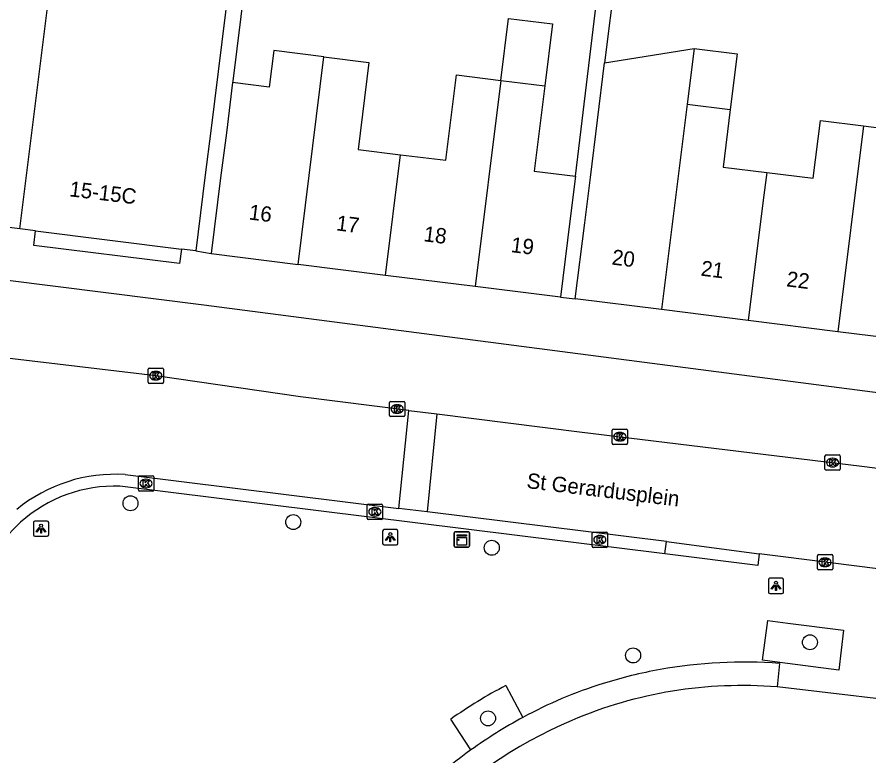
# Model space of a CAD drawing. Extents: x 161696 to 162377, y 380761 to 381673.
# Drawn here: x 162038 to 162093.7, y 381316.7 to 381365 of the extents above; entities that cross this region are included whole.
import ezdxf

# ---------------------------------------------------------------- set-up
doc = ezdxf.new("R2010")
doc.units = 0
for name, color, linetype in [('IMGEO_Boom', 7, 'Continuous'), ('IMGEO_Kast', 7, 'Continuous'), ('IMGEO_Kolk', 7, 'Continuous'), ('IMGEO_Lichtpunt', 7, 'Continuous'), ('IMGEO_Openbare_ruimte_label', 7, 'Continuous'), ('IMGEO_Pand', 7, 'Continuous'), ('IMGEO_Pand_nummerreeks', 7, 'Continuous'), ('IMGEO_Parkeervlak_open', 7, 'Continuous'), ('IMGEO_Rijbaan_lokaal_open', 7, 'Continuous'), ('IMGEO_Voetpad_open', 7, 'Continuous')]:
    doc.layers.add(name, color=color, linetype=linetype)

msp = doc.modelspace()

# ---------------------------------------------------------------- linework, layer by layer
at = {"layer": 'IMGEO_Boom'}
for centre in [(162045.423, 381333.251), (162056.062, 381332.022), (162069.042, 381330.344), (162089.839, 381324.168), (162078.282, 381323.308), (162068.796, 381319.197)]:
    msp.add_circle(centre, 0.489, dxfattribs=at)
at = {"layer": 'IMGEO_Kast'}
for p, q in [((162066.584, 381330.468), (162066.584, 381331.309)), ((162066.584, 381331.309), (162066.584, 381330.468)), ((162066.659, 381331.393), (162067.5, 381331.393)), ((162067.5, 381331.393), (162066.659, 381331.393)), ((162067.584, 381331.318), (162067.584, 381330.477)), ((162067.584, 381330.477), (162067.584, 381331.318)), ((162067.509, 381330.393), (162066.668, 381330.393)), ((162066.668, 381330.393), (162067.509, 381330.393))]:
    msp.add_line(p, q, dxfattribs=at)
for points in [[(162066.779, 381331.183), (162067.379, 381331.183), (162067.379, 381331.098), (162066.779, 381331.098), (162066.779, 381331.183)], [(162066.779, 381331.008), (162067.379, 381331.008), (162067.379, 381330.519), (162066.779, 381330.519), (162066.779, 381331.008)]]:
    msp.add_lwpolyline(points, dxfattribs=at)
msp.add_circle((162066.863, 381330.857), 0.0377, dxfattribs=at)
for centre, start, end in [((162066.662, 381331.315), 92.4484, 184.2845), ((162066.662, 381331.315), 92.4484, 184.2845), ((162067.506, 381331.315), 2.4484, 94.2845), ((162067.506, 381331.315), 2.4484, 94.2845), ((162066.662, 381330.471), 182.4484, 274.2845), ((162066.662, 381330.471), 182.4484, 274.2845), ((162067.506, 381330.471), 272.4484, 4.2845), ((162067.506, 381330.471), 272.4484, 4.2845)]:
    msp.add_arc(centre, 0.0779, start, end, dxfattribs=at)
at = {"layer": 'IMGEO_Kolk'}
for p, q in [((162046.575, 381341.162), (162046.575, 381342.014)), ((162046.65, 381342.088), (162047.502, 381342.088)), ((162047.063, 381341.868), (162047.088, 381341.868)), ((162047.576, 381342.014), (162047.576, 381341.162)), ((162047.086, 381341.308), (162047.061, 381341.308)), ((162047.502, 381341.088), (162046.65, 381341.088)), ((162062.355, 381338.986), (162062.355, 381339.838)), ((162062.43, 381339.912), (162063.282, 381339.912)), ((162062.843, 381339.692), (162062.868, 381339.692)), ((162063.356, 381339.838), (162063.356, 381338.986)), ((162062.866, 381339.132), (162062.841, 381339.132)), ((162063.282, 381338.912), (162062.43, 381338.912)), ((162076.916, 381337.175), (162076.916, 381338.027)), ((162076.991, 381338.101), (162077.843, 381338.101)), ((162077.404, 381337.881), (162077.429, 381337.881)), ((162077.917, 381338.027), (162077.917, 381337.175)), ((162077.427, 381337.321), (162077.402, 381337.321)), ((162077.843, 381337.101), (162076.991, 381337.101)), ((162090.824, 381335.484), (162090.824, 381336.336)), ((162090.899, 381336.41), (162091.751, 381336.41)), ((162091.825, 381336.336), (162091.825, 381335.484)), ((162091.312, 381336.19), (162091.337, 381336.19)), ((162091.751, 381335.41), (162090.899, 381335.41)), ((162091.335, 381335.63), (162091.31, 381335.63)), ((162045.939, 381334.119), (162045.939, 381334.971)), ((162046.014, 381335.045), (162046.866, 381335.045)), ((162046.427, 381334.825), (162046.452, 381334.825)), ((162046.94, 381334.971), (162046.94, 381334.119)), ((162046.866, 381334.045), (162046.014, 381334.045)), ((162046.45, 381334.265), (162046.425, 381334.265)), ((162060.899, 381332.269), (162060.899, 381333.121)), ((162060.974, 381333.195), (162061.826, 381333.195)), ((162061.387, 381332.975), (162061.412, 381332.975)), ((162061.9, 381333.121), (162061.9, 381332.269)), ((162061.41, 381332.415), (162061.385, 381332.415)), ((162061.826, 381332.195), (162060.974, 381332.195)), ((162075.605, 381330.442), (162075.605, 381331.294)), ((162075.68, 381331.368), (162076.532, 381331.368)), ((162076.606, 381331.294), (162076.606, 381330.442)), ((162076.093, 381331.148), (162076.118, 381331.148)), ((162076.532, 381330.368), (162075.68, 381330.368)), ((162076.116, 381330.588), (162076.091, 381330.588)), ((162090.327, 381328.968), (162090.327, 381329.82)), ((162090.402, 381329.894), (162091.254, 381329.894)), ((162090.815, 381329.674), (162090.84, 381329.674)), ((162091.328, 381329.82), (162091.328, 381328.968)), ((162090.838, 381329.114), (162090.813, 381329.114)), ((162091.254, 381328.894), (162090.402, 381328.894))]:
    msp.add_line(p, q, dxfattribs=at)
for points in [[(162046.575, 381341.162), (162046.575, 381342.014)], [(162046.65, 381342.088), (162047.502, 381342.088)], [(162046.896, 381341.788), (162047.019, 381341.788), (162047.019, 381341.637), (162047.149, 381341.788), (162047.313, 381341.788), (162047.167, 381341.637), (162047.32, 381341.388), (162047.168, 381341.388), (162047.083, 381341.552), (162047.019, 381341.485), (162047.019, 381341.388), (162046.896, 381341.388), (162046.896, 381341.788)], [(162047.576, 381342.014), (162047.576, 381341.162)], [(162047.502, 381341.088), (162046.65, 381341.088)], [(162062.355, 381338.986), (162062.355, 381339.838)], [(162062.43, 381339.912), (162063.282, 381339.912)], [(162062.676, 381339.612), (162062.799, 381339.612), (162062.799, 381339.461), (162062.929, 381339.612), (162063.093, 381339.612), (162062.947, 381339.461), (162063.1, 381339.212), (162062.948, 381339.212), (162062.863, 381339.376), (162062.799, 381339.309), (162062.799, 381339.212), (162062.676, 381339.212), (162062.676, 381339.612)], [(162063.356, 381339.838), (162063.356, 381338.986)], [(162063.282, 381338.912), (162062.43, 381338.912)], [(162076.916, 381337.175), (162076.916, 381338.027)], [(162076.991, 381338.101), (162077.843, 381338.101)], [(162077.917, 381338.027), (162077.917, 381337.175)], [(162077.237, 381337.801), (162077.36, 381337.801), (162077.36, 381337.65), (162077.49, 381337.801), (162077.654, 381337.801), (162077.508, 381337.65), (162077.661, 381337.401), (162077.509, 381337.401), (162077.424, 381337.565), (162077.36, 381337.498), (162077.36, 381337.401), (162077.237, 381337.401), (162077.237, 381337.801)], [(162077.843, 381337.101), (162076.991, 381337.101)], [(162090.824, 381335.484), (162090.824, 381336.336)], [(162090.899, 381336.41), (162091.751, 381336.41)], [(162091.825, 381336.336), (162091.825, 381335.484)], [(162091.145, 381336.11), (162091.268, 381336.11), (162091.268, 381335.959), (162091.398, 381336.11), (162091.562, 381336.11), (162091.416, 381335.959), (162091.569, 381335.71), (162091.417, 381335.71), (162091.332, 381335.874), (162091.268, 381335.807), (162091.268, 381335.71), (162091.145, 381335.71), (162091.145, 381336.11)], [(162091.751, 381335.41), (162090.899, 381335.41)], [(162045.939, 381334.119), (162045.939, 381334.971)], [(162046.014, 381335.045), (162046.866, 381335.045)], [(162046.26, 381334.745), (162046.383, 381334.745), (162046.383, 381334.594), (162046.513, 381334.745), (162046.677, 381334.745), (162046.531, 381334.594), (162046.684, 381334.345), (162046.532, 381334.345), (162046.447, 381334.509), (162046.383, 381334.442), (162046.383, 381334.345), (162046.26, 381334.345), (162046.26, 381334.745)], [(162046.94, 381334.971), (162046.94, 381334.119)], [(162046.866, 381334.045), (162046.014, 381334.045)], [(162060.899, 381332.269), (162060.899, 381333.121)], [(162060.974, 381333.195), (162061.826, 381333.195)], [(162061.22, 381332.895), (162061.343, 381332.895), (162061.343, 381332.744), (162061.473, 381332.895), (162061.637, 381332.895), (162061.491, 381332.744), (162061.644, 381332.495), (162061.492, 381332.495), (162061.407, 381332.659), (162061.343, 381332.592), (162061.343, 381332.495), (162061.22, 381332.495), (162061.22, 381332.895)], [(162061.9, 381333.121), (162061.9, 381332.269)], [(162061.826, 381332.195), (162060.974, 381332.195)], [(162075.605, 381330.442), (162075.605, 381331.294)], [(162075.68, 381331.368), (162076.532, 381331.368)], [(162076.606, 381331.294), (162076.606, 381330.442)], [(162075.926, 381331.068), (162076.049, 381331.068), (162076.049, 381330.917), (162076.179, 381331.068), (162076.343, 381331.068), (162076.197, 381330.917), (162076.35, 381330.668), (162076.198, 381330.668), (162076.113, 381330.832), (162076.049, 381330.765), (162076.049, 381330.668), (162075.926, 381330.668), (162075.926, 381331.068)], [(162076.532, 381330.368), (162075.68, 381330.368)], [(162090.327, 381328.968), (162090.327, 381329.82)], [(162090.402, 381329.894), (162091.254, 381329.894)], [(162090.648, 381329.594), (162090.771, 381329.594), (162090.771, 381329.443), (162090.901, 381329.594), (162091.065, 381329.594), (162090.919, 381329.443), (162091.072, 381329.194), (162090.92, 381329.194), (162090.835, 381329.358), (162090.771, 381329.291), (162090.771, 381329.194), (162090.648, 381329.194), (162090.648, 381329.594)], [(162091.328, 381329.82), (162091.328, 381328.968)], [(162091.254, 381328.894), (162090.402, 381328.894)]]:
    msp.add_lwpolyline(points, dxfattribs=at)
for centre, start, end in [((162046.652, 381342.012), 91.552, 178.448), ((162046.652, 381342.012), 91.552, 178.448), ((162047.5, 381342.012), 1.552, 88.448), ((162047.5, 381342.012), 1.552, 88.448), ((162046.652, 381341.164), 181.552, 268.448), ((162046.652, 381341.164), 181.552, 268.448), ((162047.5, 381341.164), 271.552, 358.448), ((162047.5, 381341.164), 271.552, 358.448), ((162062.432, 381339.836), 91.552, 178.448), ((162062.432, 381339.836), 91.552, 178.448), ((162063.28, 381339.836), 1.552, 88.448), ((162063.28, 381339.836), 1.552, 88.448), ((162062.432, 381338.988), 181.552, 268.448), ((162062.432, 381338.988), 181.552, 268.448), ((162063.28, 381338.988), 271.552, 358.448), ((162063.28, 381338.988), 271.552, 358.448), ((162076.993, 381338.025), 91.552, 178.448), ((162076.993, 381338.025), 91.552, 178.448), ((162077.841, 381338.025), 1.552, 88.448), ((162077.841, 381338.025), 1.552, 88.448), ((162076.993, 381337.177), 181.552, 268.448), ((162076.993, 381337.177), 181.552, 268.448), ((162077.841, 381337.177), 271.552, 358.448), ((162077.841, 381337.177), 271.552, 358.448), ((162090.901, 381336.334), 91.552, 178.448), ((162090.901, 381336.334), 91.552, 178.448), ((162091.749, 381336.334), 1.552, 88.448), ((162091.749, 381336.334), 1.552, 88.448), ((162090.901, 381335.486), 181.552, 268.448), ((162090.901, 381335.486), 181.552, 268.448), ((162091.749, 381335.486), 271.552, 358.448), ((162091.749, 381335.486), 271.552, 358.448), ((162046.016, 381334.969), 91.552, 178.448), ((162046.016, 381334.969), 91.552, 178.448), ((162046.864, 381334.969), 1.552, 88.448), ((162046.864, 381334.969), 1.552, 88.448), ((162046.016, 381334.121), 181.552, 268.448), ((162046.016, 381334.121), 181.552, 268.448), ((162046.864, 381334.121), 271.552, 358.448), ((162046.864, 381334.121), 271.552, 358.448), ((162060.976, 381333.119), 91.552, 178.448), ((162060.976, 381333.119), 91.552, 178.448), ((162061.824, 381333.119), 1.552, 88.448), ((162061.824, 381333.119), 1.552, 88.448), ((162060.976, 381332.271), 181.552, 268.448), ((162060.976, 381332.271), 181.552, 268.448), ((162061.824, 381332.271), 271.552, 358.448), ((162061.824, 381332.271), 271.552, 358.448), ((162075.682, 381331.292), 91.552, 178.448), ((162075.682, 381331.292), 91.552, 178.448), ((162076.53, 381331.292), 1.552, 88.448), ((162076.53, 381331.292), 1.552, 88.448), ((162075.682, 381330.444), 181.552, 268.448), ((162075.682, 381330.444), 181.552, 268.448), ((162076.53, 381330.444), 271.552, 358.448), ((162076.53, 381330.444), 271.552, 358.448), ((162090.404, 381329.818), 91.552, 178.448), ((162090.404, 381329.818), 91.552, 178.448), ((162091.252, 381329.818), 1.552, 88.448), ((162091.252, 381329.818), 1.552, 88.448), ((162090.404, 381328.97), 181.552, 268.448), ((162090.404, 381328.97), 181.552, 268.448), ((162091.252, 381328.97), 271.552, 358.448), ((162091.252, 381328.97), 271.552, 358.448)]:
    msp.add_arc(centre, 0.0765, start, end, dxfattribs=at)
for centre, major_axis, ratio, start_param, end_param in [((162047.062, 381341.588), (-0.387, 0.002), 0.722429, 4.712389, 7.853982), ((162047.087, 381341.588), (-0.39, 0.002), 0.717154, 1.570796, 4.712389), ((162062.842, 381339.412), (-0.387, 0.002), 0.722429, 4.712389, 7.853982), ((162062.867, 381339.412), (-0.39, 0.002), 0.717154, 1.570796, 4.712389), ((162077.403, 381337.601), (-0.387, 0.002), 0.722429, 4.712389, 7.853982), ((162077.428, 381337.601), (-0.39, 0.002), 0.717154, 1.570796, 4.712389), ((162091.311, 381335.91), (-0.387, 0.002), 0.722429, 4.712389, 7.853982), ((162091.336, 381335.91), (-0.39, 0.002), 0.717154, 1.570796, 4.712389), ((162046.426, 381334.545), (-0.387, 0.002), 0.722429, 4.712389, 7.853982), ((162046.451, 381334.545), (-0.39, 0.002), 0.717154, 1.570796, 4.712389), ((162061.386, 381332.695), (-0.387, 0.002), 0.722429, 4.712389, 7.853982), ((162061.411, 381332.695), (-0.39, 0.002), 0.717154, 1.570796, 4.712389), ((162076.092, 381330.868), (-0.387, 0.002), 0.722429, 4.712389, 7.853982), ((162076.117, 381330.868), (-0.39, 0.002), 0.717154, 1.570796, 4.712389), ((162090.814, 381329.394), (-0.387, 0.002), 0.722429, 4.712389, 7.853982), ((162090.839, 381329.394), (-0.39, 0.002), 0.717154, 1.570796, 4.712389)]:
    msp.add_ellipse(centre, major_axis=major_axis, ratio=ratio, start_param=start_param, end_param=end_param, dxfattribs=at)
at = {"layer": 'IMGEO_Lichtpunt'}
for p, q in [((162039.079, 381331.994), (162039.079, 381331.187)), ((162039.079, 381331.994), (162039.079, 381331.187)), ((162039.981, 381332.089), (162039.173, 381332.089)), ((162039.981, 381332.089), (162039.173, 381332.089)), ((162040.075, 381331.187), (162040.075, 381331.994)), ((162040.075, 381331.187), (162040.075, 381331.994)), ((162061.907, 381331.438), (162061.907, 381330.631)), ((162061.907, 381331.438), (162061.907, 381330.631)), ((162062.809, 381331.533), (162062.001, 381331.533)), ((162062.809, 381331.533), (162062.001, 381331.533)), ((162062.903, 381330.631), (162062.903, 381331.438)), ((162062.903, 381330.631), (162062.903, 381331.438)), ((162039.173, 381331.093), (162039.981, 381331.093)), ((162039.173, 381331.093), (162039.981, 381331.093)), ((162062.001, 381330.537), (162062.809, 381330.537)), ((162062.001, 381330.537), (162062.809, 381330.537)), ((162087.123, 381328.258), (162087.123, 381327.451)), ((162087.123, 381328.258), (162087.123, 381327.451)), ((162088.025, 381328.353), (162087.217, 381328.353)), ((162088.025, 381328.353), (162087.217, 381328.353)), ((162088.119, 381327.451), (162088.119, 381328.258)), ((162088.119, 381327.451), (162088.119, 381328.258)), ((162087.217, 381327.357), (162088.025, 381327.357)), ((162087.217, 381327.357), (162088.025, 381327.357))]:
    msp.add_line(p, q, dxfattribs=at)
for points in [[(162039.453, 381331.658), (162039.492, 381331.63), (162039.304, 381331.368), (162039.266, 381331.395), (162039.453, 381331.658)], [(162039.555, 381331.61), (162039.602, 381331.61), (162039.602, 381331.288), (162039.555, 381331.288), (162039.555, 381331.61)], [(162039.665, 381331.63), (162039.703, 381331.657), (162039.89, 381331.395), (162039.851, 381331.367), (162039.665, 381331.63)], [(162062.281, 381331.102), (162062.32, 381331.074), (162062.132, 381330.812), (162062.094, 381330.839), (162062.281, 381331.102)], [(162062.383, 381331.054), (162062.43, 381331.054), (162062.43, 381330.732), (162062.383, 381330.732), (162062.383, 381331.054)], [(162062.493, 381331.074), (162062.531, 381331.101), (162062.718, 381330.839), (162062.679, 381330.811), (162062.493, 381331.074)], [(162087.497, 381327.922), (162087.536, 381327.894), (162087.348, 381327.632), (162087.31, 381327.659), (162087.497, 381327.922)], [(162087.599, 381327.874), (162087.646, 381327.874), (162087.646, 381327.552), (162087.599, 381327.552), (162087.599, 381327.874)], [(162087.709, 381327.894), (162087.747, 381327.921), (162087.934, 381327.659), (162087.895, 381327.631), (162087.709, 381327.894)]]:
    msp.add_lwpolyline(points, dxfattribs=at)
for centre in [(162039.578, 381331.792), (162062.406, 381331.236), (162087.622, 381328.056)]:
    msp.add_circle(centre, 0.0994, dxfattribs=at)
for centre, start, end in [((162039.173, 381331.994), 90, 180), ((162039.173, 381331.994), 90, 180), ((162039.981, 381331.994), 0, 90), ((162039.981, 381331.994), 0, 90), ((162039.173, 381331.187), 180, 270), ((162039.173, 381331.187), 180, 270), ((162039.981, 381331.187), 270, 0), ((162039.981, 381331.187), 270, 360), ((162062.001, 381331.438), 90, 180), ((162062.001, 381331.438), 90, 180), ((162062.809, 381331.438), 0, 90), ((162062.809, 381331.438), 0, 90), ((162062.001, 381330.631), 180, 270), ((162062.001, 381330.631), 180, 270), ((162062.809, 381330.631), 270, 0), ((162062.809, 381330.631), 270, 360), ((162087.217, 381328.258), 90, 180), ((162087.217, 381328.258), 90, 180), ((162088.025, 381328.258), 0, 90), ((162088.025, 381328.258), 0, 90), ((162087.217, 381327.451), 180, 270), ((162087.217, 381327.451), 180, 270), ((162088.025, 381327.451), 270, 0), ((162088.025, 381327.451), 270, 360)]:
    msp.add_arc(centre, 0.0946, start, end, dxfattribs=at)
at = {"layer": 'IMGEO_Pand'}
for points in [[(162038.184, 381351.173), (162041.121, 381374.73)], [(162052.623, 381373.299), (162050.669, 381357.597), (162050.309, 381354.704), (162049.692, 381349.742)], [(162069.634, 381360.885), (162070.138, 381364.937), (162073.02, 381364.579), (162072.516, 381360.527)], [(162076.421, 381362.024), (162082.273, 381362.963)], [(162082.273, 381362.963), (162081.822, 381359.333)], [(162082.273, 381362.963), (162085.087, 381362.613), (162084.636, 381358.983)], [(162058.072, 381362.417), (162054.784, 381362.826), (162054.487, 381360.44), (162052.1, 381360.737)], [(162056.385, 381348.852), (162058.072, 381362.417)], [(162058.072, 381362.417), (162061.013, 381362.051), (162060.307, 381356.373), (162063.077, 381356.029)], [(162074.501, 381346.608), (162075.12, 381351.58), (162075.487, 381354.527), (162076.421, 381362.024)], [(162052.1, 381360.737), (162051.693, 381357.466), (162051.306, 381354.523), (162050.689, 381349.561)], [(162063.077, 381356.029), (162066.032, 381355.661), (162066.727, 381361.247), (162069.634, 381360.885)], [(162069.634, 381360.885), (162067.959, 381347.413)], [(162069.634, 381360.885), (162072.516, 381360.527)], [(162072.516, 381360.527), (162071.823, 381354.955), (162074.51, 381354.62)], [(162081.822, 381359.333), (162080.142, 381345.904)], [(162081.822, 381359.333), (162084.636, 381358.983)], [(162084.636, 381358.983), (162084.169, 381355.223), (162087.012, 381354.869)], [(162087.012, 381354.869), (162090.053, 381354.49), (162090.521, 381358.254), (162093.349, 381357.903)], [(162093.349, 381357.903), (162091.668, 381344.464)], [(162093.349, 381357.903), (162096.355, 381357.529), (162096, 381354.675), (162098.464, 381354.37)], [(162062.096, 381348.142), (162063.077, 381356.029)], [(162074.51, 381354.62), (162074.144, 381351.682), (162073.527, 381346.72)], [(162087.012, 381354.869), (162086.786, 381353.06), (162085.802, 381345.197)], [(162038.184, 381351.173), (162032.644, 381351.863)], [(162039.223, 381351.044), (162038.184, 381351.173)], [(162039.223, 381351.044), (162048.75, 381349.859)], [(162049.692, 381349.742), (162048.75, 381349.859)], [(162050.689, 381349.561), (162056.385, 381348.852)], [(162062.096, 381348.142), (162056.385, 381348.852)], [(162067.959, 381347.413), (162062.096, 381348.142)], [(162073.527, 381346.72), (162067.959, 381347.413)], [(162080.142, 381345.904), (162074.501, 381346.608)], [(162085.802, 381345.197), (162080.142, 381345.904)], [(162091.668, 381344.464), (162085.802, 381345.197)], [(162097.346, 381343.755), (162091.668, 381344.464)]]:
    msp.add_lwpolyline(points, dxfattribs=at)
at = {"layer": 'IMGEO_Parkeervlak_open'}
for points in [[(162086.743, 381322.996), (162087.084, 381325.588), (162088.404, 381325.418), (162092.026, 381324.952), (162091.725, 381322.357), (162087.872, 381322.851), (162086.743, 381322.996)], [(162087.861, 381322.791), (162087.688, 381321.254)], [(162069.959, 381321.343), (162071.07, 381319.254)], [(162098.405, 381319.984), (162087.688, 381321.254)], [(162067.677, 381317.134), (162066.356, 381319.139)]]:
    msp.add_lwpolyline(points, dxfattribs=at)
for centre, radius, start, end in [((162085.537, 381292.07), 30.808, 85.6735, 100.2721), ((162085.383, 381292.535), 30.324, 100.1434, 107.377), ((162084.503, 381293.519), 31.396, 117.5978, 125.3115), ((162085.428, 381292.209), 30.648, 107.2737, 112.6721), ((162085.438, 381292.838), 28.505, 85.4723, 113.0615), ((162086.084, 381291.564), 31.498, 113.3216, 118.4674), ((162086.26, 381291.042), 30.479, 113.1606, 158.6778), ((162086.267, 381291.157), 31.944, 118.4074, 125.5882), ((162086.474, 381290.883), 32.287, 125.6045, 137.2606)]:
    msp.add_arc(centre, radius, start, end, dxfattribs=at)
at = {"layer": 'IMGEO_Rijbaan_lokaal_open'}
for points in [[(162063.609, 381339.316), (162056.547, 381340.198), (162047.076, 381341.587), (162032.552, 381343.303)], [(162062.963, 381332.914), (162063.609, 381339.316)], [(162063.609, 381339.316), (162065.452, 381339.086)], [(162065.452, 381339.086), (162064.815, 381332.685)], [(162065.452, 381339.086), (162074.769, 381337.922), (162093.232, 381335.677), (162105.621, 381334.084)], [(162045.073, 381335.125), (162062.963, 381332.914)], [(162080.352, 381329.942), (162044.729, 381334.364)], [(162064.815, 381332.685), (162062.963, 381332.914)], [(162080.457, 381330.751), (162064.815, 381332.685)], [(162080.352, 381329.942), (162080.457, 381330.751)], [(162080.457, 381330.751), (162086.517, 381329.954)], [(162114.399, 381326.425), (162088.101, 381329.762), (162086.517, 381329.954)]]:
    msp.add_lwpolyline(points, dxfattribs=at)
for centre, radius, start, end in [((162044.42, 381325.001), 10.145, 86.3119, 129.3055), ((162044.368, 381325.243), 9.128, 87.731, 132.1828), ((162044.009, 381325.541), 8.667, 131.7467, 168.9691)]:
    msp.add_arc(centre, radius, start, end, dxfattribs=at)
at = {"layer": 'IMGEO_Voetpad_open'}
for points in [[(162071.138, 381372.231), (162053.786, 381374.326), (162053.669, 381373.359), (162052.113, 381360.842), (162052.1, 381360.737)], [(162074.51, 381354.62), (162076.391, 381370.198), (162070.971, 381370.852), (162071.138, 381372.231)], [(162077.135, 381367.757), (162076.421, 381362.024)], [(162048.75, 381349.859), (162048.633, 381348.918), (162039.106, 381350.103), (162039.223, 381351.044)], [(162049.692, 381349.742), (162050.689, 381349.561)], [(162033.579, 381344.268), (162034.083, 381348.235), (162050.222, 381346.217), (162096.616, 381340.187)], [(162073.527, 381346.72), (162074.501, 381346.608)], [(162086.517, 381329.954), (162086.427, 381329.176), (162080.352, 381329.942)]]:
    msp.add_lwpolyline(points, dxfattribs=at)

# ---------------------------------------------------------------- texts
at = {"layer": 'IMGEO_Openbare_ruimte_label'}
msp.add_text('St Gerardusplein', height=1, rotation=353.0526, dxfattribs=at).set_placement((162071.284, 381334.248))
at = {"layer": 'IMGEO_Pand_nummerreeks'}
for s, rotation, p in [('15-15C', 353.0648, (162041.391, 381353.314)), ('16', 352.9068, (162053.125, 381351.798)), ('17', 352.9089, (162058.835, 381351.087)), ('18', 352.9089, (162064.548, 381350.377)), ('19', 352.9089, (162070.254, 381349.667)), ('20', 352.8815, (162076.852, 381348.854)), ('21', 352.8839, (162082.672, 381348.128)), ('22', 352.8839, (162088.268, 381347.429))]:
    msp.add_text(s, height=1, rotation=rotation, dxfattribs=at).set_placement(p)

doc.saveas('drawing.dxf')
